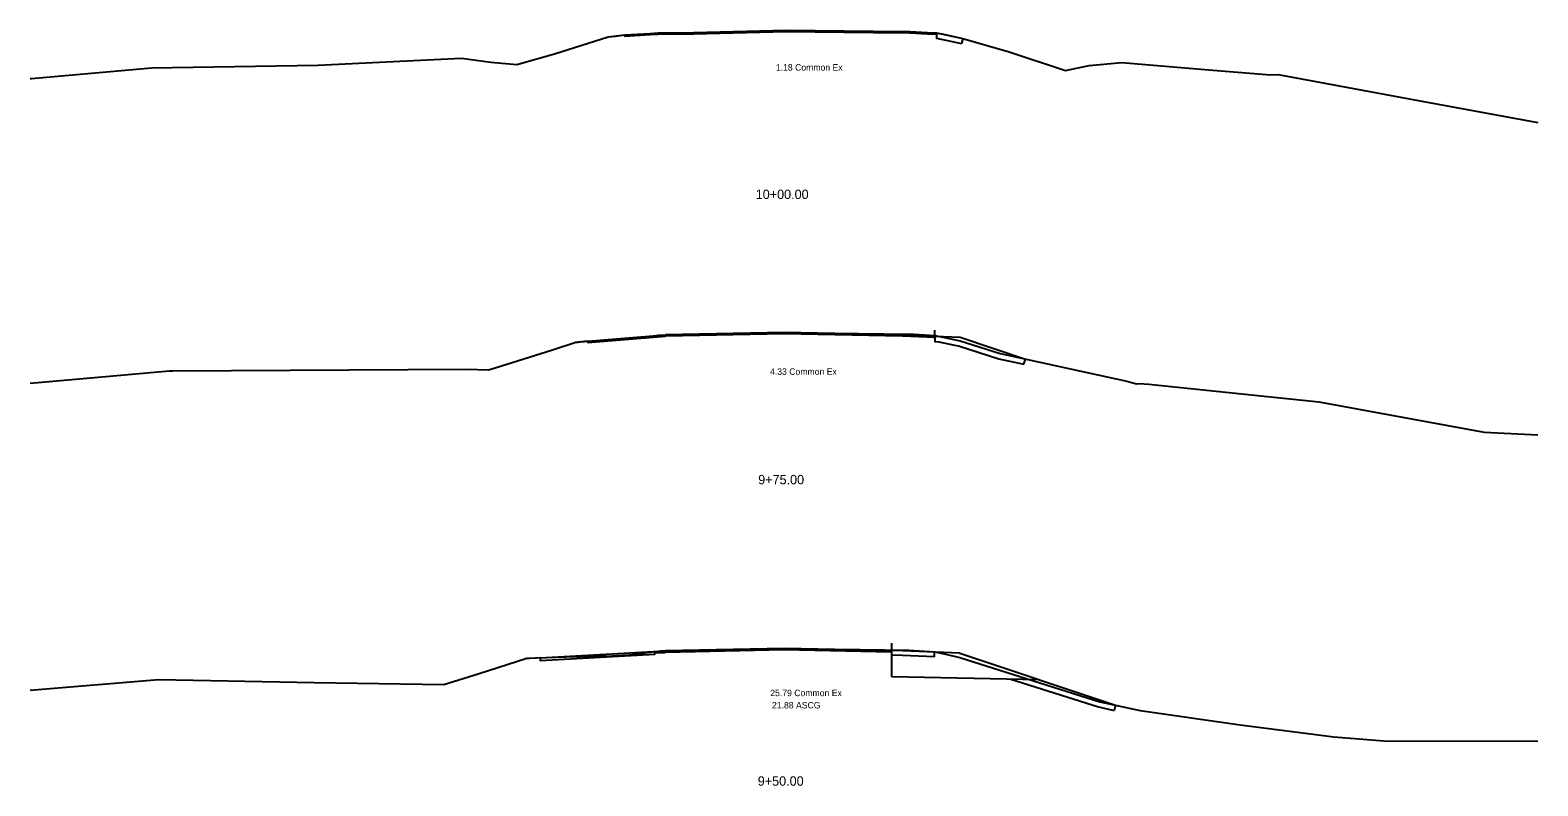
# Model space of a CAD drawing. Extents: x 2194738 to 2195190, y 863888 to 863998.
# Drawn here: x 2195050.3 to 2195190.3, y 863895.1 to 863965.3 of the extents above; entities that cross this region are included whole.
import ezdxf

# ---------------------------------------------------------------- set-up
doc = ezdxf.new("R2010")
doc.units = 0
for name, color, linetype in [('Approach', 7, 'Continuous'), ('H_V ANNOTATION', 7, 'Continuous'), ('Junk', 7, 'Continuous'), ('S_Roadway_Centerline', 7, 'Continuous'), ('TEMPLATE', 7, 'Continuous')]:
    doc.layers.add(name, color=color, linetype=linetype)

msp = doc.modelspace()

# ---------------------------------------------------------------- linework, layer by layer
at = {"layer": 'Junk'}
for p, q in [((2195134.26, 863936.51), (2195134.26, 863937.39)), ((2195130.26, 863906.34), (2195130.26, 863908.31))]:
    msp.add_line(p, q, dxfattribs=at)
at = {"layer": 'S_Roadway_Centerline'}
for points in [[(2195050.26, 863960.77), (2195050.37, 863960.78), (2195061.52, 863961.77), (2195076.97, 863962.01), (2195090.31, 863962.67), (2195093.04, 863962.28), (2195095.45, 863962.08), (2195098.94, 863963.07), (2195103.93, 863964.63), (2195104.61, 863964.7), (2195105.48, 863964.83), (2195107.82, 863964.96), (2195108.57, 863965.01), (2195111.88, 863965.04), (2195120.43, 863965.26), (2195128.56, 863965.17), (2195131.94, 863965.12), (2195133.58, 863965.03), (2195134.43, 863965), (2195135.21, 863964.84), (2195136.85, 863964.49), (2195141.15, 863963.24), (2195146.41, 863961.52), (2195148.6, 863961.96), (2195151.63, 863962.25), (2195159.7, 863961.56), (2195165.43, 863961.1), (2195166.15, 863961.14), (2195178.3, 863958.87), (2195190.26, 863956.68)], [(2195050.26, 863932.47), (2195057.62, 863933.11), (2195063.17, 863933.6), (2195063.5, 863933.61), (2195090.78, 863933.77), (2195092.82, 863933.71), (2195093.45, 863933.9), (2195098.76, 863935.55), (2195100.92, 863936.26), (2195101.13, 863936.28), (2195101.34, 863936.29), (2195104.63, 863936.56), (2195106.71, 863936.68), (2195108.57, 863936.91), (2195118.35, 863937.14), (2195120.34, 863937.17), (2195122.33, 863937.14), (2195131.93, 863937.03), (2195132.34, 863937.01), (2195134.26, 863936.9), (2195136.19, 863936.5), (2195136.6, 863936.4), (2195140.33, 863935.22), (2195152.09, 863932.66), (2195153, 863932.41), (2195153.24, 863932.43), (2195154.12, 863932.36), (2195169.91, 863930.73), (2195185.26, 863927.92), (2195190.26, 863927.66)], [(2195050.26, 863903.95), (2195062.16, 863904.93), (2195076.64, 863904.66), (2195088.68, 863904.48), (2195091.95, 863905.5), (2195096.37, 863906.93), (2195100, 863907.04), (2195104.29, 863907.13), (2195105.87, 863907.24), (2195108.79, 863907.59), (2195113.32, 863907.7), (2195120.3, 863907.81), (2195127.31, 863907.71), (2195131.88, 863907.66), (2195133.31, 863907.57), (2195134.22, 863907.52), (2195135.13, 863907.33), (2195136.59, 863906.99), (2195149.58, 863902.87), (2195153.33, 863902.06), (2195162.6, 863900.74), (2195171.31, 863899.62), (2195175.97, 863899.25), (2195190.26, 863899.22)]]:
    msp.add_lwpolyline(points, dxfattribs=at)
at = {"layer": 'TEMPLATE'}
for p, q in [((2195103.93, 863964.63), (2195105.48, 863964.83)), ((2195134.43, 863965), (2195136.85, 863964.49)), ((2195136.85, 863964.49), (2195136.75, 863964.01)), ((2195102.03, 863936.36), (2195101.13, 863936.28)), ((2195102.03, 863936.36), (2195109.26, 863936.95)), ((2195109.26, 863936.95), (2195120.26, 863937.17)), ((2195120.26, 863937.17), (2195109.26, 863936.95)), ((2195120.26, 863937.04), (2195109.26, 863936.82)), ((2195131.26, 863936.95), (2195120.26, 863937.17)), ((2195131.26, 863936.82), (2195120.26, 863937.04)), ((2195134.26, 863936.83), (2195131.26, 863936.95)), ((2195134.26, 863936.7), (2195131.26, 863936.82)), ((2195134.26, 863936.83), (2195134.26, 863936.7)), ((2195134.26, 863936.83), (2195136.6, 863936.73)), ((2195136.6, 863936.73), (2195142.69, 863934.71)), ((2195109.26, 863907.59), (2195120.26, 863907.81)), ((2195120.26, 863907.81), (2195109.26, 863907.59)), ((2195131.26, 863907.59), (2195120.26, 863907.81)), ((2195097.6, 863906.95), (2195096.2, 863906.87)), ((2195120.26, 863907.68), (2195109.26, 863907.46)), ((2195130.26, 863907.48), (2195120.26, 863907.68)), ((2195130.26, 863905.19), (2195130.26, 863907.48)), ((2195131.26, 863907.17), (2195130.26, 863907.19)), ((2195136.59, 863907.37), (2195131.26, 863907.59)), ((2195134.22, 863907.05), (2195131.26, 863907.17)), ((2195134.22, 863907.05), (2195134.22, 863907.47)), ((2195143.96, 863904.92), (2195130.26, 863905.19)), ((2195151.03, 863902.56), (2195150.92, 863902.07))]:
    msp.add_line(p, q, dxfattribs=at)
for points in [[(2195105.48, 863964.83), (2195107.82, 863964.96), (2195108.57, 863965.01), (2195111.88, 863965.04), (2195120.43, 863965.26), (2195128.56, 863965.17), (2195131.94, 863965.12), (2195133.58, 863965.03), (2195134.43, 863965), (2195134.43, 863965)], [(2195105.48, 863964.83), (2195105.48, 863964.7), (2195107.82, 863964.84), (2195108.57, 863964.88), (2195111.88, 863964.92), (2195120.43, 863965.13), (2195128.56, 863965.04), (2195131.94, 863965), (2195133.58, 863964.91), (2195134.43, 863964.87), (2195134.43, 863965), (2195134.43, 863964.87)], [(2195134.43, 863965), (2195134.43, 863964.5), (2195136.75, 863964.01)], [(2195102.03, 863936.36), (2195102.03, 863936.23), (2195109.26, 863936.82)], [(2195134.26, 863936.7), (2195134.26, 863936.33), (2195134.64, 863936.31)], [(2195134.64, 863936.31), (2195136.08, 863936.01), (2195136.47, 863935.92), (2195140.2, 863934.74), (2195142.53, 863934.23)], [(2195142.53, 863934.23), (2195142.69, 863934.71)], [(2195097.6, 863906.95), (2195109.26, 863907.59)], [(2195097.6, 863906.95), (2195097.6, 863906.7), (2195108.26, 863907.3), (2195108.26, 863907.42)], [(2195108.26, 863907.42), (2195109.26, 863907.46)], [(2195136.59, 863907.37), (2195151.03, 863902.56)], [(2195141.32, 863904.97), (2195149.45, 863902.39), (2195150.92, 863902.07)]]:
    msp.add_lwpolyline(points, dxfattribs=at)

# ---------------------------------------------------------------- texts
at = {"layer": 'Approach'}
for s, p in [('1.18 Common Ex', (2195119.5, 863961.5)), ('4.33 Common Ex', (2195118.96, 863933.24)), ('25.79 Common Ex', (2195118.98, 863903.39)), ('21.88 ASCG', (2195119.14, 863902.25))]:
    msp.add_text(s, height=0.6, dxfattribs=at).set_placement(p)
at = {"layer": 'H_V ANNOTATION'}
for s, p in [('10+00.00', (2195117.63, 863949.57)), ('9+75.00', (2195117.86, 863923.07)), ('9+50.00', (2195117.82, 863895.07))]:
    msp.add_text(s, height=0.875, dxfattribs=at).set_placement(p)

doc.saveas('drawing.dxf')
